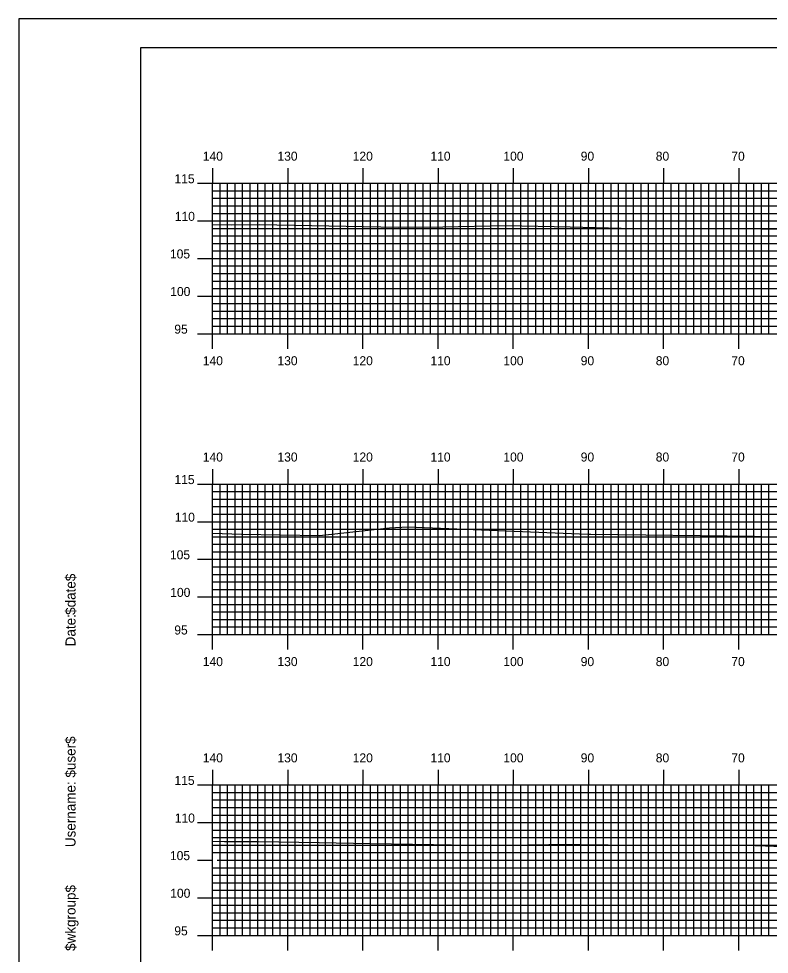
# Model space of a CAD drawing. Extents: x 1779106 to 1779449, y 442591 to 442811.
# Drawn here: x 1779105.5 to 1779205.4, y 442686.2 to 442810.5 of the extents above; entities that cross this region are included whole.
import ezdxf

# ---------------------------------------------------------------- set-up
doc = ezdxf.new("R2010")
doc.units = 0
for name, color, linetype in [('BORDER', 7, 'Continuous'), ('H_V ANNOTATION', 7, 'Continuous'), ('MAJOR', 7, 'Continuous'), ('MINOR', 7, 'Continuous'), ('PLOT BOUNDARY', 7, 'Continuous'), ('S_Roadway_Centerline', 7, 'Continuous')]:
    doc.layers.add(name, color=color, linetype=linetype)

msp = doc.modelspace()

# ---------------------------------------------------------------- linework, layer by layer
at = {"layer": 'BORDER'}
msp.add_lwpolyline([(1779121.73, 442596.67), (1779441.73, 442596.67), (1779441.73, 442806.67), (1779121.73, 442806.67)], close=True, dxfattribs=at)
at = {"layer": 'MAJOR'}
for p, q in [((1779131.33, 442790.67), (1779131.33, 442788.67)), ((1779141.33, 442790.67), (1779141.33, 442788.67)), ((1779151.33, 442790.67), (1779151.33, 442788.67)), ((1779161.33, 442790.67), (1779161.33, 442788.67)), ((1779171.33, 442790.67), (1779171.33, 442788.67)), ((1779181.33, 442790.67), (1779181.33, 442788.67)), ((1779191.33, 442790.67), (1779191.33, 442788.67)), ((1779201.33, 442790.67), (1779201.33, 442788.67)), ((1779129.33, 442788.67), (1779131.33, 442788.67)), ((1779131.33, 442788.67), (1779411.33, 442788.67)), ((1779131.33, 442768.67), (1779131.33, 442788.67)), ((1779131.33, 442768.67), (1779131.33, 442788.67)), ((1779131.33, 442788.67), (1779411.33, 442788.67)), ((1779141.33, 442768.67), (1779141.33, 442788.67)), ((1779151.33, 442768.67), (1779151.33, 442788.67)), ((1779161.33, 442768.67), (1779161.33, 442788.67)), ((1779171.33, 442768.67), (1779171.33, 442788.67)), ((1779181.33, 442768.67), (1779181.33, 442788.67)), ((1779191.33, 442768.67), (1779191.33, 442788.67)), ((1779201.33, 442768.67), (1779201.33, 442788.67)), ((1779129.33, 442783.67), (1779131.33, 442783.67)), ((1779131.33, 442783.67), (1779411.33, 442783.67)), ((1779129.33, 442778.67), (1779131.33, 442778.67)), ((1779131.33, 442778.67), (1779411.33, 442778.67)), ((1779129.33, 442773.67), (1779131.33, 442773.67)), ((1779131.33, 442773.67), (1779411.33, 442773.67)), ((1779129.33, 442768.67), (1779131.33, 442768.67)), ((1779131.33, 442768.67), (1779411.33, 442768.67)), ((1779131.33, 442768.67), (1779411.33, 442768.67)), ((1779131.33, 442766.66), (1779131.33, 442768.67)), ((1779141.33, 442766.66), (1779141.33, 442768.67)), ((1779151.33, 442766.66), (1779151.33, 442768.67)), ((1779161.33, 442766.66), (1779161.33, 442768.67)), ((1779171.33, 442766.66), (1779171.33, 442768.67)), ((1779181.33, 442766.66), (1779181.33, 442768.67)), ((1779191.33, 442766.66), (1779191.33, 442768.67)), ((1779201.33, 442766.66), (1779201.33, 442768.67)), ((1779131.33, 442750.67), (1779131.33, 442748.67)), ((1779141.33, 442750.67), (1779141.33, 442748.67)), ((1779151.33, 442750.67), (1779151.33, 442748.67)), ((1779161.33, 442750.67), (1779161.33, 442748.67)), ((1779171.33, 442750.67), (1779171.33, 442748.67)), ((1779181.33, 442750.67), (1779181.33, 442748.67)), ((1779191.33, 442750.67), (1779191.33, 442748.67)), ((1779201.33, 442750.67), (1779201.33, 442748.67)), ((1779129.33, 442748.67), (1779131.33, 442748.67)), ((1779131.33, 442748.67), (1779411.33, 442748.67)), ((1779131.33, 442728.67), (1779131.33, 442748.67)), ((1779131.33, 442728.67), (1779131.33, 442748.67)), ((1779131.33, 442748.67), (1779411.33, 442748.67)), ((1779141.33, 442728.67), (1779141.33, 442748.67)), ((1779151.33, 442728.67), (1779151.33, 442748.67)), ((1779161.33, 442728.67), (1779161.33, 442748.67)), ((1779171.33, 442728.67), (1779171.33, 442748.67)), ((1779181.33, 442728.67), (1779181.33, 442748.67)), ((1779191.33, 442728.67), (1779191.33, 442748.67)), ((1779201.33, 442728.67), (1779201.33, 442748.67)), ((1779129.33, 442743.67), (1779131.33, 442743.67)), ((1779131.33, 442743.67), (1779411.33, 442743.67)), ((1779129.33, 442738.67), (1779131.33, 442738.67)), ((1779131.33, 442738.67), (1779411.33, 442738.67)), ((1779129.33, 442733.67), (1779131.33, 442733.67)), ((1779131.33, 442733.67), (1779411.33, 442733.67)), ((1779129.33, 442728.67), (1779131.33, 442728.67)), ((1779131.33, 442728.67), (1779411.33, 442728.67)), ((1779131.33, 442728.67), (1779411.33, 442728.67)), ((1779131.33, 442726.66), (1779131.33, 442728.67)), ((1779141.33, 442726.66), (1779141.33, 442728.67)), ((1779151.33, 442726.66), (1779151.33, 442728.67)), ((1779161.33, 442726.66), (1779161.33, 442728.67)), ((1779171.33, 442726.66), (1779171.33, 442728.67)), ((1779181.33, 442726.66), (1779181.33, 442728.67)), ((1779191.33, 442726.66), (1779191.33, 442728.67)), ((1779201.33, 442726.66), (1779201.33, 442728.67)), ((1779131.33, 442710.67), (1779131.33, 442708.67)), ((1779141.33, 442710.67), (1779141.33, 442708.67)), ((1779151.33, 442710.67), (1779151.33, 442708.67)), ((1779161.33, 442710.67), (1779161.33, 442708.67)), ((1779171.33, 442710.67), (1779171.33, 442708.67)), ((1779181.33, 442710.67), (1779181.33, 442708.67)), ((1779191.33, 442710.67), (1779191.33, 442708.67)), ((1779201.33, 442710.67), (1779201.33, 442708.67)), ((1779129.33, 442708.67), (1779131.33, 442708.67)), ((1779131.33, 442708.67), (1779411.33, 442708.67)), ((1779131.33, 442688.67), (1779131.33, 442708.67)), ((1779131.33, 442688.67), (1779131.33, 442708.67)), ((1779131.33, 442708.67), (1779411.33, 442708.67)), ((1779141.33, 442688.67), (1779141.33, 442708.67)), ((1779151.33, 442688.67), (1779151.33, 442708.67)), ((1779161.33, 442688.67), (1779161.33, 442708.67)), ((1779171.33, 442688.67), (1779171.33, 442708.67)), ((1779181.33, 442688.67), (1779181.33, 442708.67)), ((1779191.33, 442688.67), (1779191.33, 442708.67)), ((1779201.33, 442688.67), (1779201.33, 442708.67)), ((1779129.33, 442703.67), (1779131.33, 442703.67)), ((1779131.33, 442703.67), (1779411.33, 442703.67)), ((1779129.33, 442698.67), (1779131.33, 442698.67)), ((1779131.96, 442698.67), (1779411.96, 442698.67)), ((1779129.33, 442693.67), (1779131.33, 442693.67)), ((1779131.33, 442693.67), (1779411.33, 442693.67)), ((1779129.33, 442688.67), (1779131.33, 442688.67)), ((1779131.33, 442688.67), (1779411.33, 442688.67)), ((1779131.33, 442688.67), (1779411.33, 442688.67)), ((1779131.33, 442686.66), (1779131.33, 442688.67)), ((1779141.33, 442686.66), (1779141.33, 442688.67)), ((1779151.33, 442686.66), (1779151.33, 442688.67)), ((1779161.33, 442686.66), (1779161.33, 442688.67)), ((1779171.33, 442686.66), (1779171.33, 442688.67)), ((1779181.33, 442686.66), (1779181.33, 442688.67)), ((1779191.33, 442686.66), (1779191.33, 442688.67)), ((1779201.33, 442686.66), (1779201.33, 442688.67))]:
    msp.add_line(p, q, dxfattribs=at)
at = {"layer": 'MINOR'}
for p, q in [((1779132.33, 442768.67), (1779132.33, 442788.67)), ((1779133.33, 442768.67), (1779133.33, 442788.67)), ((1779134.33, 442768.67), (1779134.33, 442788.67)), ((1779135.33, 442768.67), (1779135.33, 442788.67)), ((1779136.33, 442768.67), (1779136.33, 442788.67)), ((1779137.33, 442768.67), (1779137.33, 442788.67)), ((1779138.33, 442768.67), (1779138.33, 442788.67)), ((1779139.33, 442768.67), (1779139.33, 442788.67)), ((1779140.33, 442768.67), (1779140.33, 442788.67)), ((1779142.33, 442768.67), (1779142.33, 442788.67)), ((1779143.33, 442768.67), (1779143.33, 442788.67)), ((1779144.33, 442768.67), (1779144.33, 442788.67)), ((1779145.33, 442768.67), (1779145.33, 442788.67)), ((1779146.33, 442768.67), (1779146.33, 442788.67)), ((1779147.33, 442768.67), (1779147.33, 442788.67)), ((1779148.33, 442768.67), (1779148.33, 442788.67)), ((1779149.33, 442768.67), (1779149.33, 442788.67)), ((1779150.33, 442768.67), (1779150.33, 442788.67)), ((1779152.33, 442768.67), (1779152.33, 442788.67)), ((1779153.33, 442768.67), (1779153.33, 442788.67)), ((1779154.33, 442768.67), (1779154.33, 442788.67)), ((1779155.33, 442768.67), (1779155.33, 442788.67)), ((1779156.33, 442768.67), (1779156.33, 442788.67)), ((1779157.33, 442768.67), (1779157.33, 442788.67)), ((1779158.33, 442768.67), (1779158.33, 442788.67)), ((1779159.33, 442768.67), (1779159.33, 442788.67)), ((1779160.33, 442768.67), (1779160.33, 442788.67)), ((1779162.33, 442768.67), (1779162.33, 442788.67)), ((1779163.33, 442768.67), (1779163.33, 442788.67)), ((1779164.33, 442768.67), (1779164.33, 442788.67)), ((1779165.33, 442768.67), (1779165.33, 442788.67)), ((1779166.33, 442768.67), (1779166.33, 442788.67)), ((1779167.33, 442768.67), (1779167.33, 442788.67)), ((1779168.33, 442768.67), (1779168.33, 442788.67)), ((1779169.33, 442768.67), (1779169.33, 442788.67)), ((1779170.33, 442768.67), (1779170.33, 442788.67)), ((1779172.33, 442768.67), (1779172.33, 442788.67)), ((1779173.33, 442768.67), (1779173.33, 442788.67)), ((1779174.33, 442768.67), (1779174.33, 442788.67)), ((1779175.33, 442768.67), (1779175.33, 442788.67)), ((1779176.33, 442768.67), (1779176.33, 442788.67)), ((1779177.33, 442768.67), (1779177.33, 442788.67)), ((1779178.33, 442768.67), (1779178.33, 442788.67)), ((1779179.33, 442768.67), (1779179.33, 442788.67)), ((1779180.33, 442768.67), (1779180.33, 442788.67)), ((1779182.33, 442768.67), (1779182.33, 442788.67)), ((1779183.33, 442768.67), (1779183.33, 442788.67)), ((1779184.33, 442768.67), (1779184.33, 442788.67)), ((1779185.33, 442768.67), (1779185.33, 442788.67)), ((1779186.33, 442768.67), (1779186.33, 442788.67)), ((1779187.33, 442768.67), (1779187.33, 442788.67)), ((1779188.33, 442768.67), (1779188.33, 442788.67)), ((1779189.33, 442768.67), (1779189.33, 442788.67)), ((1779190.33, 442768.67), (1779190.33, 442788.67)), ((1779192.33, 442768.67), (1779192.33, 442788.67)), ((1779193.33, 442768.67), (1779193.33, 442788.67)), ((1779194.33, 442768.67), (1779194.33, 442788.67)), ((1779195.33, 442768.67), (1779195.33, 442788.67)), ((1779196.33, 442768.67), (1779196.33, 442788.67)), ((1779197.33, 442768.67), (1779197.33, 442788.67)), ((1779198.33, 442768.67), (1779198.33, 442788.67)), ((1779199.33, 442768.67), (1779199.33, 442788.67)), ((1779200.33, 442768.67), (1779200.33, 442788.67)), ((1779202.33, 442768.67), (1779202.33, 442788.67)), ((1779203.33, 442768.67), (1779203.33, 442788.67)), ((1779204.33, 442768.67), (1779204.33, 442788.67)), ((1779205.33, 442768.67), (1779205.33, 442788.67)), ((1779131.33, 442787.67), (1779411.33, 442787.67)), ((1779131.33, 442787.67), (1779133.33, 442787.67)), ((1779131.33, 442786.67), (1779411.33, 442786.67)), ((1779131.33, 442786.67), (1779133.33, 442786.67)), ((1779131.33, 442785.67), (1779411.33, 442785.67)), ((1779131.33, 442785.67), (1779133.33, 442785.67)), ((1779131.33, 442784.67), (1779411.33, 442784.67)), ((1779131.33, 442784.67), (1779133.33, 442784.67)), ((1779131.33, 442782.67), (1779411.33, 442782.67)), ((1779131.33, 442782.67), (1779133.33, 442782.67)), ((1779131.33, 442781.67), (1779411.33, 442781.67)), ((1779131.33, 442781.67), (1779133.33, 442781.67)), ((1779131.33, 442780.67), (1779411.33, 442780.67)), ((1779131.33, 442780.67), (1779133.33, 442780.67)), ((1779131.33, 442779.67), (1779411.33, 442779.67)), ((1779131.33, 442779.67), (1779133.33, 442779.67)), ((1779131.33, 442777.67), (1779411.33, 442777.67)), ((1779131.33, 442777.67), (1779133.33, 442777.67)), ((1779131.33, 442776.67), (1779411.33, 442776.67)), ((1779131.33, 442776.67), (1779133.33, 442776.67)), ((1779131.33, 442775.67), (1779411.33, 442775.67)), ((1779131.33, 442775.67), (1779133.33, 442775.67)), ((1779131.33, 442774.67), (1779411.33, 442774.67)), ((1779131.33, 442774.67), (1779133.33, 442774.67)), ((1779131.33, 442772.67), (1779411.33, 442772.67)), ((1779131.33, 442772.67), (1779133.33, 442772.67)), ((1779131.33, 442771.67), (1779411.33, 442771.67)), ((1779131.33, 442771.67), (1779133.33, 442771.67)), ((1779131.33, 442770.67), (1779411.33, 442770.67)), ((1779131.33, 442770.67), (1779133.33, 442770.67)), ((1779131.33, 442769.67), (1779411.33, 442769.67)), ((1779131.33, 442769.67), (1779133.33, 442769.67)), ((1779132.33, 442728.67), (1779132.33, 442748.67)), ((1779133.33, 442728.67), (1779133.33, 442748.67)), ((1779134.33, 442728.67), (1779134.33, 442748.67)), ((1779135.33, 442728.67), (1779135.33, 442748.67)), ((1779136.33, 442728.67), (1779136.33, 442748.67)), ((1779137.33, 442728.67), (1779137.33, 442748.67)), ((1779138.33, 442728.67), (1779138.33, 442748.67)), ((1779139.33, 442728.67), (1779139.33, 442748.67)), ((1779140.33, 442728.67), (1779140.33, 442748.67)), ((1779142.33, 442728.67), (1779142.33, 442748.67)), ((1779143.33, 442728.67), (1779143.33, 442748.67)), ((1779144.33, 442728.67), (1779144.33, 442748.67)), ((1779145.33, 442728.67), (1779145.33, 442748.67)), ((1779146.33, 442728.67), (1779146.33, 442748.67)), ((1779147.33, 442728.67), (1779147.33, 442748.67)), ((1779148.33, 442728.67), (1779148.33, 442748.67)), ((1779149.33, 442728.67), (1779149.33, 442748.67)), ((1779150.33, 442728.67), (1779150.33, 442748.67)), ((1779152.33, 442728.67), (1779152.33, 442748.67)), ((1779153.33, 442728.67), (1779153.33, 442748.67)), ((1779154.33, 442728.67), (1779154.33, 442748.67)), ((1779155.33, 442728.67), (1779155.33, 442748.67)), ((1779156.33, 442728.67), (1779156.33, 442748.67)), ((1779157.33, 442728.67), (1779157.33, 442748.67)), ((1779158.33, 442728.67), (1779158.33, 442748.67)), ((1779159.33, 442728.67), (1779159.33, 442748.67)), ((1779160.33, 442728.67), (1779160.33, 442748.67)), ((1779162.33, 442728.67), (1779162.33, 442748.67)), ((1779163.33, 442728.67), (1779163.33, 442748.67)), ((1779164.33, 442728.67), (1779164.33, 442748.67)), ((1779165.33, 442728.67), (1779165.33, 442748.67)), ((1779166.33, 442728.67), (1779166.33, 442748.67)), ((1779167.33, 442728.67), (1779167.33, 442748.67)), ((1779168.33, 442728.67), (1779168.33, 442748.67)), ((1779169.33, 442728.67), (1779169.33, 442748.67)), ((1779170.33, 442728.67), (1779170.33, 442748.67)), ((1779172.33, 442728.67), (1779172.33, 442748.67)), ((1779173.33, 442728.67), (1779173.33, 442748.67)), ((1779174.33, 442728.67), (1779174.33, 442748.67)), ((1779175.33, 442728.67), (1779175.33, 442748.67)), ((1779176.33, 442728.67), (1779176.33, 442748.67)), ((1779177.33, 442728.67), (1779177.33, 442748.67)), ((1779178.33, 442728.67), (1779178.33, 442748.67)), ((1779179.33, 442728.67), (1779179.33, 442748.67)), ((1779180.33, 442728.67), (1779180.33, 442748.67)), ((1779182.33, 442728.67), (1779182.33, 442748.67)), ((1779183.33, 442728.67), (1779183.33, 442748.67)), ((1779184.33, 442728.67), (1779184.33, 442748.67)), ((1779185.33, 442728.67), (1779185.33, 442748.67)), ((1779186.33, 442728.67), (1779186.33, 442748.67)), ((1779187.33, 442728.67), (1779187.33, 442748.67)), ((1779188.33, 442728.67), (1779188.33, 442748.67)), ((1779189.33, 442728.67), (1779189.33, 442748.67)), ((1779190.33, 442728.67), (1779190.33, 442748.67)), ((1779192.33, 442728.67), (1779192.33, 442748.67)), ((1779193.33, 442728.67), (1779193.33, 442748.67)), ((1779194.33, 442728.67), (1779194.33, 442748.67)), ((1779195.33, 442728.67), (1779195.33, 442748.67)), ((1779196.33, 442728.67), (1779196.33, 442748.67)), ((1779197.33, 442728.67), (1779197.33, 442748.67)), ((1779198.33, 442728.67), (1779198.33, 442748.67)), ((1779199.33, 442728.67), (1779199.33, 442748.67)), ((1779200.33, 442728.67), (1779200.33, 442748.67)), ((1779202.33, 442728.67), (1779202.33, 442748.67)), ((1779203.33, 442728.67), (1779203.33, 442748.67)), ((1779204.33, 442728.67), (1779204.33, 442748.67)), ((1779205.33, 442728.67), (1779205.33, 442748.67)), ((1779131.33, 442747.67), (1779411.33, 442747.67)), ((1779131.33, 442747.67), (1779133.33, 442747.67)), ((1779131.33, 442746.67), (1779411.33, 442746.67)), ((1779131.33, 442746.67), (1779133.33, 442746.67)), ((1779131.33, 442745.67), (1779411.33, 442745.67)), ((1779131.33, 442745.67), (1779133.33, 442745.67)), ((1779131.33, 442744.67), (1779411.33, 442744.67)), ((1779131.33, 442744.67), (1779133.33, 442744.67)), ((1779131.33, 442742.67), (1779411.33, 442742.67)), ((1779131.33, 442742.67), (1779133.33, 442742.67)), ((1779131.33, 442741.67), (1779411.33, 442741.67)), ((1779131.33, 442741.67), (1779133.33, 442741.67)), ((1779131.33, 442740.67), (1779411.33, 442740.67)), ((1779131.33, 442740.67), (1779133.33, 442740.67)), ((1779131.33, 442739.67), (1779411.33, 442739.67)), ((1779131.33, 442739.67), (1779133.33, 442739.67)), ((1779131.33, 442737.67), (1779411.33, 442737.67)), ((1779131.33, 442737.67), (1779133.33, 442737.67)), ((1779131.33, 442736.67), (1779411.33, 442736.67)), ((1779131.33, 442736.67), (1779133.33, 442736.67)), ((1779131.33, 442735.67), (1779411.33, 442735.67)), ((1779131.33, 442735.67), (1779133.33, 442735.67)), ((1779131.33, 442734.67), (1779411.33, 442734.67)), ((1779131.33, 442734.67), (1779133.33, 442734.67)), ((1779131.33, 442732.67), (1779411.33, 442732.67)), ((1779131.33, 442732.67), (1779133.33, 442732.67)), ((1779131.33, 442731.67), (1779411.33, 442731.67)), ((1779131.33, 442731.67), (1779133.33, 442731.67)), ((1779131.33, 442730.67), (1779411.33, 442730.67)), ((1779131.33, 442730.67), (1779133.33, 442730.67)), ((1779131.33, 442729.67), (1779411.33, 442729.67)), ((1779131.33, 442729.67), (1779133.33, 442729.67)), ((1779132.33, 442688.67), (1779132.33, 442708.67)), ((1779133.33, 442688.67), (1779133.33, 442708.67)), ((1779134.33, 442688.67), (1779134.33, 442708.67)), ((1779135.33, 442688.67), (1779135.33, 442708.67)), ((1779136.33, 442688.67), (1779136.33, 442708.67)), ((1779137.33, 442688.67), (1779137.33, 442708.67)), ((1779138.33, 442688.67), (1779138.33, 442708.67)), ((1779139.33, 442688.67), (1779139.33, 442708.67)), ((1779140.33, 442688.67), (1779140.33, 442708.67)), ((1779142.33, 442688.67), (1779142.33, 442708.67)), ((1779143.33, 442688.67), (1779143.33, 442708.67)), ((1779144.33, 442688.67), (1779144.33, 442708.67)), ((1779145.33, 442688.67), (1779145.33, 442708.67)), ((1779146.33, 442688.67), (1779146.33, 442708.67)), ((1779147.33, 442688.67), (1779147.33, 442708.67)), ((1779148.33, 442688.67), (1779148.33, 442708.67)), ((1779149.33, 442688.67), (1779149.33, 442708.67)), ((1779150.33, 442688.67), (1779150.33, 442708.67)), ((1779152.33, 442688.67), (1779152.33, 442708.67)), ((1779153.33, 442688.67), (1779153.33, 442708.67)), ((1779154.33, 442688.67), (1779154.33, 442708.67)), ((1779155.33, 442688.67), (1779155.33, 442708.67)), ((1779156.33, 442688.67), (1779156.33, 442708.67)), ((1779157.33, 442688.67), (1779157.33, 442708.67)), ((1779158.33, 442688.67), (1779158.33, 442708.67)), ((1779159.33, 442688.67), (1779159.33, 442708.67)), ((1779160.33, 442688.67), (1779160.33, 442708.67)), ((1779162.33, 442688.67), (1779162.33, 442708.67)), ((1779163.33, 442688.67), (1779163.33, 442708.67)), ((1779164.33, 442688.67), (1779164.33, 442708.67)), ((1779165.33, 442688.67), (1779165.33, 442708.67)), ((1779166.33, 442688.67), (1779166.33, 442708.67)), ((1779167.33, 442688.67), (1779167.33, 442708.67)), ((1779168.33, 442688.67), (1779168.33, 442708.67)), ((1779169.33, 442688.67), (1779169.33, 442708.67)), ((1779170.33, 442688.67), (1779170.33, 442708.67)), ((1779172.33, 442688.67), (1779172.33, 442708.67)), ((1779173.33, 442688.67), (1779173.33, 442708.67)), ((1779174.33, 442688.67), (1779174.33, 442708.67)), ((1779175.33, 442688.67), (1779175.33, 442708.67)), ((1779176.33, 442688.67), (1779176.33, 442708.67)), ((1779177.33, 442688.67), (1779177.33, 442708.67)), ((1779178.33, 442688.67), (1779178.33, 442708.67)), ((1779179.33, 442688.67), (1779179.33, 442708.67)), ((1779180.33, 442688.67), (1779180.33, 442708.67)), ((1779182.33, 442688.67), (1779182.33, 442708.67)), ((1779183.33, 442688.67), (1779183.33, 442708.67)), ((1779184.33, 442688.67), (1779184.33, 442708.67)), ((1779185.33, 442688.67), (1779185.33, 442708.67)), ((1779186.33, 442688.67), (1779186.33, 442708.67)), ((1779187.33, 442688.67), (1779187.33, 442708.67)), ((1779188.33, 442688.67), (1779188.33, 442708.67)), ((1779189.33, 442688.67), (1779189.33, 442708.67)), ((1779190.33, 442688.67), (1779190.33, 442708.67)), ((1779192.33, 442688.67), (1779192.33, 442708.67)), ((1779193.33, 442688.67), (1779193.33, 442708.67)), ((1779194.33, 442688.67), (1779194.33, 442708.67)), ((1779195.33, 442688.67), (1779195.33, 442708.67)), ((1779196.33, 442688.67), (1779196.33, 442708.67)), ((1779197.33, 442688.67), (1779197.33, 442708.67)), ((1779198.33, 442688.67), (1779198.33, 442708.67)), ((1779199.33, 442688.67), (1779199.33, 442708.67)), ((1779200.33, 442688.67), (1779200.33, 442708.67)), ((1779202.33, 442688.67), (1779202.33, 442708.67)), ((1779203.33, 442688.67), (1779203.33, 442708.67)), ((1779204.33, 442688.67), (1779204.33, 442708.67)), ((1779205.33, 442688.67), (1779205.33, 442708.67)), ((1779131.33, 442707.67), (1779411.33, 442707.67)), ((1779131.33, 442707.67), (1779133.33, 442707.67)), ((1779131.33, 442706.67), (1779411.33, 442706.67)), ((1779131.33, 442706.67), (1779133.33, 442706.67)), ((1779131.33, 442705.67), (1779411.33, 442705.67)), ((1779131.33, 442705.67), (1779133.33, 442705.67)), ((1779131.33, 442704.67), (1779411.33, 442704.67)), ((1779131.33, 442704.67), (1779133.33, 442704.67)), ((1779131.33, 442702.67), (1779411.33, 442702.67)), ((1779131.33, 442702.67), (1779133.33, 442702.67)), ((1779131.33, 442701.67), (1779411.33, 442701.67)), ((1779131.33, 442701.67), (1779133.33, 442701.67)), ((1779131.33, 442700.67), (1779411.33, 442700.67)), ((1779131.33, 442700.67), (1779133.33, 442700.67)), ((1779131.33, 442699.67), (1779411.33, 442699.67)), ((1779131.33, 442699.67), (1779133.33, 442699.67)), ((1779131.33, 442697.67), (1779411.33, 442697.67)), ((1779131.33, 442697.67), (1779133.33, 442697.67)), ((1779131.33, 442696.67), (1779411.33, 442696.67)), ((1779131.33, 442696.67), (1779133.33, 442696.67)), ((1779131.33, 442695.67), (1779411.33, 442695.67)), ((1779131.33, 442695.67), (1779133.33, 442695.67)), ((1779131.33, 442694.67), (1779411.33, 442694.67)), ((1779131.33, 442694.67), (1779133.33, 442694.67)), ((1779131.33, 442692.67), (1779411.33, 442692.67)), ((1779131.33, 442692.67), (1779133.33, 442692.67)), ((1779131.33, 442691.67), (1779411.33, 442691.67)), ((1779131.33, 442691.67), (1779133.33, 442691.67)), ((1779131.33, 442690.67), (1779411.33, 442690.67)), ((1779131.33, 442690.67), (1779133.33, 442690.67)), ((1779131.33, 442689.67), (1779411.33, 442689.67)), ((1779131.33, 442689.67), (1779133.33, 442689.67))]:
    msp.add_line(p, q, dxfattribs=at)
at = {"layer": 'PLOT BOUNDARY'}
msp.add_lwpolyline([(1779105.54, 442590.55), (1779445.54, 442590.55), (1779445.54, 442810.55), (1779105.54, 442810.55)], close=True, dxfattribs=at)
at = {"layer": 'S_Roadway_Centerline'}
for points in [[(1779131.33, 442783.2), (1779133.85, 442783.16), (1779137.55, 442783.18), (1779156, 442782.85), (1779161.97, 442782.86), (1779170.32, 442783.05), (1779178.9, 442782.88), (1779185.67, 442782.72), (1779201.43, 442782.67), (1779204.32, 442782.63), (1779208.38, 442782.57)], [(1779131.33, 442742.14), (1779135.18, 442742.01), (1779145.55, 442741.85), (1779154.86, 442742.85), (1779157.31, 442742.97), (1779181.23, 442742.03), (1779181.46, 442742.03), (1779181.66, 442742.03), (1779185.34, 442741.98), (1779203.4, 442741.75), (1779205.43, 442741.66)], [(1779131.33, 442701.18), (1779132.92, 442701.17), (1779137.46, 442701.16), (1779145.49, 442701.02), (1779152.34, 442700.9), (1779160.72, 442700.73), (1779167.87, 442700.6), (1779176.08, 442700.75), (1779180.16, 442700.76), (1779183.93, 442700.72), (1779202.07, 442700.67), (1779204.87, 442700.58), (1779214.72, 442700.17)]]:
    msp.add_lwpolyline(points, dxfattribs=at)

# ---------------------------------------------------------------- texts
at = {"layer": 'BORDER'}
for s, p in [('$date$', (1779113.1, 442731.28)), ('Date:', (1779113.1, 442727.1)), ('$user$', (1779113.1, 442709.65)), ('Username:', (1779113.1, 442700.4)), ('$wkgroup$', (1779113.1, 442686.6))]:
    msp.add_text(s, height=1.339, rotation=90, dxfattribs=at).set_placement(p)
at = {"layer": 'H_V ANNOTATION'}
for s, p in [('140', (1779130.03, 442791.67)), ('130', (1779139.96, 442791.67)), ('120', (1779149.97, 442791.67)), ('110', (1779160.31, 442791.67)), ('100', (1779170.01, 442791.67)), ('90', (1779180.3, 442791.67)), ('80', (1779190.28, 442791.67)), ('70', (1779200.33, 442791.67)), ('115', (1779126.26, 442788.67)), ('110', (1779126.3, 442783.67)), ('105', (1779125.66, 442778.67)), ('100', (1779125.7, 442773.67)), ('95', (1779126.24, 442768.67)), ('140', (1779130.03, 442764.47)), ('130', (1779139.96, 442764.47)), ('120', (1779149.97, 442764.47)), ('110', (1779160.31, 442764.47)), ('100', (1779170.01, 442764.47)), ('90', (1779180.3, 442764.47)), ('80', (1779190.28, 442764.47)), ('70', (1779200.33, 442764.47)), ('140', (1779130.03, 442751.67)), ('130', (1779139.96, 442751.67)), ('120', (1779149.97, 442751.67)), ('110', (1779160.31, 442751.67)), ('100', (1779170.01, 442751.67)), ('90', (1779180.3, 442751.67)), ('80', (1779190.28, 442751.67)), ('70', (1779200.33, 442751.67)), ('115', (1779126.26, 442748.67)), ('110', (1779126.3, 442743.67)), ('105', (1779125.66, 442738.67)), ('100', (1779125.7, 442733.67)), ('95', (1779126.24, 442728.67)), ('140', (1779130.03, 442724.47)), ('130', (1779139.96, 442724.47)), ('120', (1779149.97, 442724.47)), ('110', (1779160.31, 442724.47)), ('100', (1779170.01, 442724.47)), ('90', (1779180.3, 442724.47)), ('80', (1779190.28, 442724.47)), ('70', (1779200.33, 442724.47)), ('140', (1779130.03, 442711.67)), ('130', (1779139.96, 442711.67)), ('120', (1779149.97, 442711.67)), ('110', (1779160.31, 442711.67)), ('100', (1779170.01, 442711.67)), ('90', (1779180.3, 442711.67)), ('80', (1779190.28, 442711.67)), ('70', (1779200.33, 442711.67)), ('115', (1779126.26, 442708.67)), ('110', (1779126.3, 442703.67)), ('105', (1779125.66, 442698.67)), ('100', (1779125.7, 442693.67)), ('95', (1779126.24, 442688.67))]:
    msp.add_text(s, height=1.2, dxfattribs=at).set_placement(p)
at = {"layer": 'MAJOR'}
for p in [(1779131.32, 442768.67), (1779131.32, 442728.67), (1779131.32, 442688.67)]:
    msp.add_text('-', height=0.012, dxfattribs=at).set_placement(p)

doc.saveas('drawing.dxf')
